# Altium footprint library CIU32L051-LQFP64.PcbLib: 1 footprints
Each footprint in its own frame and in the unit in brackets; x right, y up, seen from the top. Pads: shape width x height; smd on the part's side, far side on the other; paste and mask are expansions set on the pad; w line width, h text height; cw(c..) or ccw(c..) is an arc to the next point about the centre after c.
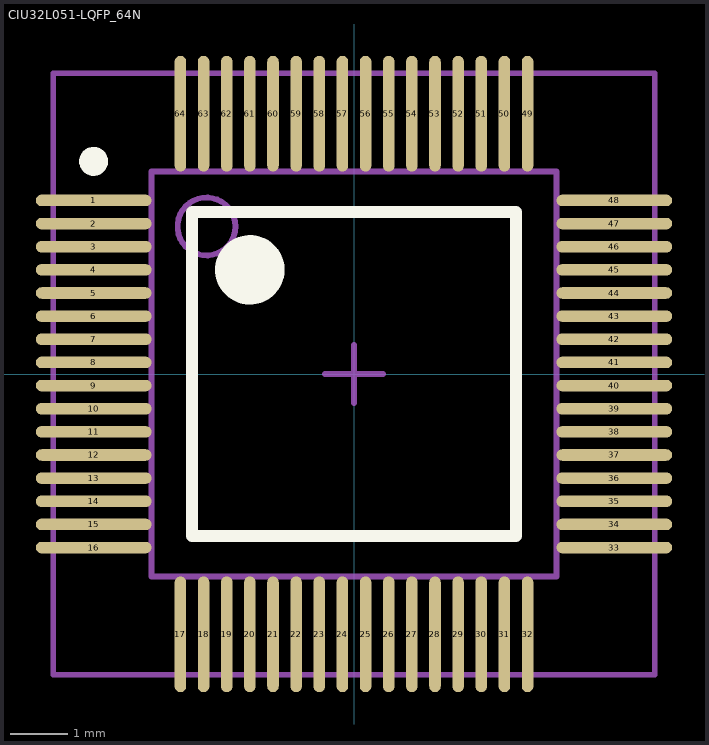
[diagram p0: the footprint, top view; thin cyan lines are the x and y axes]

## CIU32L051-LQFP_64N [mm] "pin间距小于0.2，pin2pin不能阻焊"
height 1.4
pads (64):
  oval 2x0.2 smd: 1(-4.5,3) 2(-4.5,2.6) 3(-4.5,2.2) 4(-4.5,1.8) 5(-4.5,1.4) 6(-4.5,1) 7(-4.5,0.6) 8(-4.5,0.2) 9(-4.5,-0.2) 10(-4.5,-0.6) 11(-4.5,-1) 12(-4.5,-1.4) 13(-4.5,-1.8) 14(-4.5,-2.2) 15(-4.5,-2.6) 16(-4.5,-3) 33(4.5,-3) 34(4.5,-2.6) 35(4.5,-2.2) 36(4.5,-1.8) 37(4.5,-1.4) 38(4.5,-1) 39(4.5,-0.6) 40(4.5,-0.2) 41(4.5,0.2) 42(4.5,0.6) 43(4.5,1) 44(4.5,1.4) 45(4.5,1.8) 46(4.5,2.2) 47(4.5,2.6) 48(4.5,3)
  oval 0.2x2 smd: 17(-3,-4.5) 18(-2.6,-4.5) 19(-2.2,-4.5) 20(-1.8,-4.5) 21(-1.4,-4.5) 22(-1,-4.5) 23(-0.6,-4.5) 24(-0.2,-4.5) 25(0.2,-4.5) 26(0.6,-4.5) 27(1,-4.5) 28(1.4,-4.5) 29(1.8,-4.5) 30(2.2,-4.5) 31(2.6,-4.5) 32(3,-4.5) 49(3,4.5) 50(2.6,4.5) 51(2.2,4.5) 52(1.8,4.5) 53(1.4,4.5) 54(1,4.5) 55(0.6,4.5) 56(0.2,4.5) 57(-0.2,4.5) 58(-0.6,4.5) 59(-1,4.5) 60(-1.4,4.5) 61(-1.8,4.5) 62(-2.2,4.5) 63(-2.6,4.5) 64(-3,4.5)
Top Overlay:
  circle w0.25: c-4.5,3.675 r0.125
  circle w0.6: c-1.8,1.8 r0.3
  lines w0.2: -2.8,-2.8 -2.8,2.8 2.8,2.8 2.8,-2.8 -2.8,-2.8
Mechanical 13:
  circle w0.1: c-2.55,2.55 r0.5
  lines w0.1: -3.5,-3.5 -3.5,3.5 3.5,3.5 3.5,-3.5 -3.5,-3.5
Mechanical 15:
  lines w0.1: -0.5,0 0.5,0 ; 0,-0.5 0,0.5 ; -5.2,-5.2 -5.2,5.2 5.2,5.2 5.2,-5.2 -5.2,-5.2
3D body: height 1.4, standoff 0.15, extent -3.5,-3.5 3.5,3.5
